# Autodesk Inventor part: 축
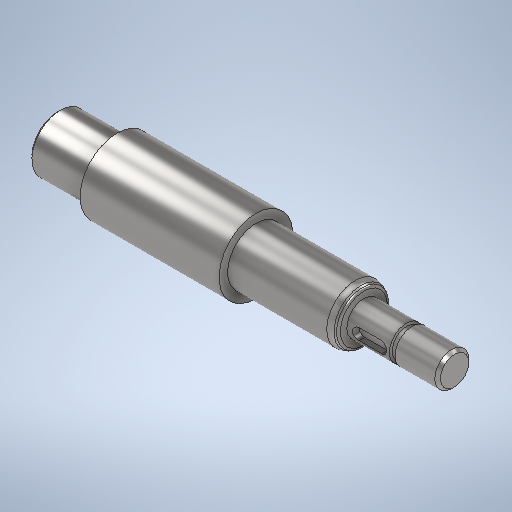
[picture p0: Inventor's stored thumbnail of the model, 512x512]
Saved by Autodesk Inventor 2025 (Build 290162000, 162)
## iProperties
Created: 2024-08
Part Number: 축
Material: 강철, 연강
Document SubType Name: Modeling
Designer: deana
Density: 7.86 g/cm^3
Appearance: 기본값
Author: jhkim
Sending System: Autodesk Inventor 2025
Preprocessor: ST-DEVELOPER v20
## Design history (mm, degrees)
feature "솔리드2"
node "솔리드1"
